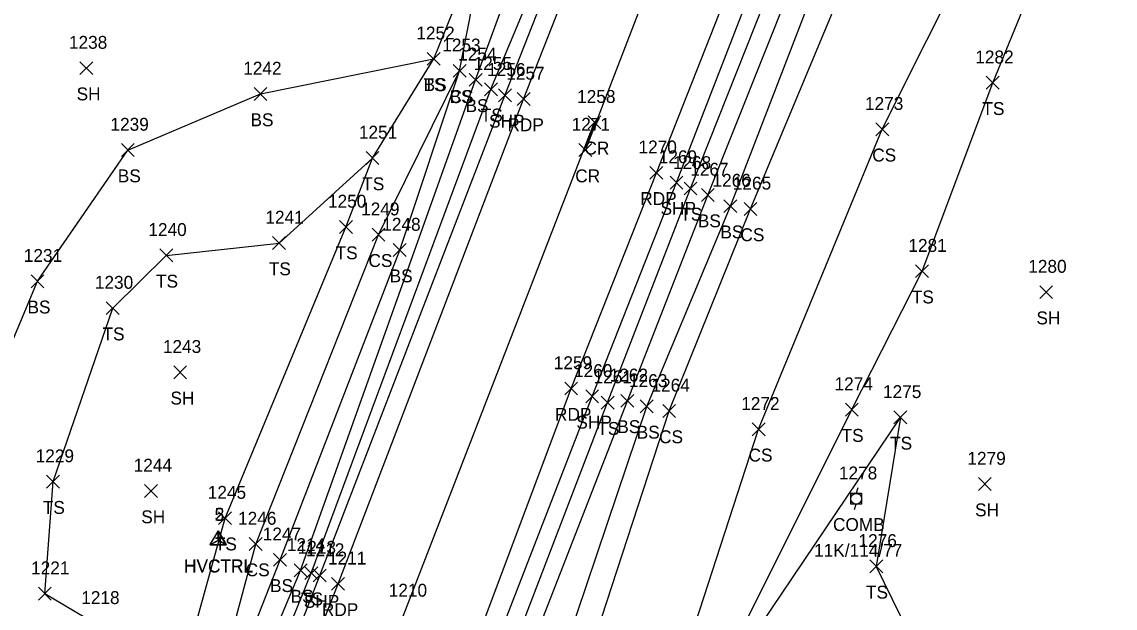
# Model space of a CAD drawing. Extents: x 1554917 to 1555870, y 813367 to 816333.
# Drawn here: x 1555023.3 to 1555192.9, y 813668.8 to 813759.7 of the extents above; entities that cross this region are included whole.
import ezdxf

# ---------------------------------------------------------------- set-up
doc = ezdxf.new("R2010")
doc.units = 0
for name, color, linetype in [('C_A', 7, 'Continuous'), ('C_I', 7, 'Continuous'), ('CPSM', 7, 'Continuous'), ('L_A', 7, 'Continuous'), ('L_I', 7, 'Continuous'), ('L_TIC', 7, 'Continuous'), ('LELB', 7, 'Continuous'), ('P_A', 7, 'Continuous'), ('P_I', 7, 'Continuous'), ('P_TIC', 7, 'Continuous'), ('PET', 7, 'Continuous'), ('PRC', 7, 'Continuous'), ('PSP', 7, 'Continuous'), ('U_A', 7, 'Continuous'), ('U_C', 7, 'Continuous'), ('U_I', 7, 'Continuous'), ('UP', 7, 'Continuous')]:
    doc.layers.add(name, color=color, linetype=linetype)

msp = doc.modelspace()

# ---------------------------------------------------------------- linework, layer by layer
at = {"layer": 'CPSM'}
for p, q in [((1555052.5, 813678.55), (1555053.75, 813680.71)), ((1555052.52, 813678.6), (1555053.77, 813680.76)), ((1555055, 813678.55), (1555053.75, 813680.71)), ((1555053.75, 813679.27), (1555053.75, 813680.71)), ((1555055.02, 813678.6), (1555053.77, 813680.76)), ((1555053.77, 813679.32), (1555053.77, 813680.76)), ((1555052.5, 813678.55), (1555053.75, 813679.27)), ((1555052.5, 813678.55), (1555055, 813678.55)), ((1555052.52, 813678.6), (1555053.77, 813679.32)), ((1555052.52, 813678.6), (1555055.02, 813678.6)), ((1555053.75, 813679.27), (1555053.75, 813679.27)), ((1555053.75, 813679.27), (1555055, 813678.55)), ((1555053.77, 813679.32), (1555053.77, 813679.32)), ((1555053.77, 813679.32), (1555055.02, 813678.6))]:
    msp.add_line(p, q, dxfattribs=at)
at = {"layer": 'L_TIC'}
for points in [[(1555086.17, 813752.94), (1555088.17, 813754.94)], [(1555088.17, 813752.94), (1555086.17, 813754.94)], [(1555086.17, 813752.94), (1555088.17, 813754.94)], [(1555088.17, 813752.94), (1555086.17, 813754.94)], [(1555032.29, 813751.5), (1555034.29, 813753.5)], [(1555034.29, 813751.5), (1555032.29, 813753.5)], [(1555090.18, 813751.08), (1555092.18, 813753.08)], [(1555092.18, 813751.08), (1555090.18, 813753.08)], [(1555090.18, 813751.08), (1555092.18, 813753.08)], [(1555092.18, 813751.08), (1555090.18, 813753.08)], [(1555092.66, 813749.68), (1555094.66, 813751.68)], [(1555094.66, 813749.68), (1555092.66, 813751.68)], [(1555095.05, 813748.22), (1555097.05, 813750.22)], [(1555097.05, 813748.22), (1555095.05, 813750.22)], [(1555172.86, 813749.23), (1555174.86, 813751.23)], [(1555174.86, 813749.23), (1555172.86, 813751.23)], [(1555059.31, 813747.49), (1555061.31, 813749.49)], [(1555061.31, 813747.49), (1555059.31, 813749.49)], [(1555155.74, 813742.02), (1555157.74, 813744.02)], [(1555157.74, 813742.02), (1555155.74, 813744.02)], [(1555038.73, 813738.79), (1555040.73, 813740.79)], [(1555040.73, 813738.79), (1555038.73, 813740.79)], [(1555076.68, 813737.56), (1555078.68, 813739.56)], [(1555078.68, 813737.56), (1555076.68, 813739.56)], [(1555076.68, 813737.56), (1555078.68, 813739.56)], [(1555078.68, 813737.56), (1555076.68, 813739.56)], [(1555126, 813732.84), (1555128, 813734.84)], [(1555128, 813732.84), (1555126, 813734.84)], [(1555128.69, 813731.82), (1555130.69, 813733.82)], [(1555130.69, 813731.82), (1555128.69, 813733.82)], [(1555132.19, 813730.1), (1555134.19, 813732.1)], [(1555134.19, 813730.1), (1555132.19, 813732.1)], [(1555135.3, 813729.66), (1555137.3, 813731.66)], [(1555137.3, 813729.66), (1555135.3, 813731.66)], [(1555072.55, 813726.86), (1555074.55, 813728.86)], [(1555074.55, 813726.86), (1555072.55, 813728.86)], [(1555077.61, 813725.66), (1555079.61, 813727.66)], [(1555079.61, 813725.66), (1555077.61, 813727.66)], [(1555062.18, 813724.38), (1555064.18, 813726.38)], [(1555064.18, 813724.38), (1555062.18, 813726.38)], [(1555044.69, 813722.46), (1555046.69, 813724.46)], [(1555046.69, 813722.46), (1555044.69, 813724.46)], [(1555080.89, 813723.28), (1555082.89, 813725.28)], [(1555082.89, 813723.28), (1555080.89, 813725.28)], [(1555161.91, 813720.01), (1555163.91, 813722.01)], [(1555163.91, 813720.01), (1555161.91, 813722.01)], [(1555024.72, 813718.45), (1555026.72, 813720.45)], [(1555026.72, 813718.45), (1555024.72, 813720.45)], [(1555181.16, 813716.76), (1555183.16, 813718.76)], [(1555183.16, 813716.76), (1555181.16, 813718.76)], [(1555036.39, 813714.28), (1555038.39, 813716.28)], [(1555038.39, 813714.28), (1555036.39, 813716.28)], [(1555046.85, 813704.33), (1555048.85, 813706.33)], [(1555048.85, 813704.33), (1555046.85, 813706.33)], [(1555113.13, 813699.62), (1555115.13, 813701.62)], [(1555115.13, 813699.62), (1555113.13, 813701.62)], [(1555116.2, 813699.9), (1555118.2, 813701.9)], [(1555118.2, 813699.9), (1555116.2, 813701.9)], [(1555119.2, 813699.04), (1555121.2, 813701.04)], [(1555121.2, 813699.04), (1555119.2, 813701.04)], [(1555151.02, 813698.54), (1555153.02, 813700.54)], [(1555153.02, 813698.54), (1555151.02, 813700.54)], [(1555122.68, 813698.33), (1555124.68, 813700.33)], [(1555124.68, 813698.33), (1555122.68, 813700.33)], [(1555158.54, 813697.33), (1555160.54, 813699.33)], [(1555160.54, 813697.33), (1555158.54, 813699.33)], [(1555136.56, 813695.49), (1555138.56, 813697.49)], [(1555138.56, 813695.49), (1555136.56, 813697.49)], [(1555027.13, 813687.37), (1555029.13, 813689.37)], [(1555029.13, 813687.37), (1555027.13, 813689.37)], [(1555171.64, 813686.99), (1555173.64, 813688.99)], [(1555173.64, 813686.99), (1555171.64, 813688.99)], [(1555042.32, 813685.92), (1555044.32, 813687.92)], [(1555044.32, 813685.92), (1555042.32, 813687.92)], [(1555053.81, 813681.71), (1555055.81, 813683.71)], [(1555055.81, 813681.71), (1555053.81, 813683.71)], [(1555058.57, 813677.69), (1555060.57, 813679.69)], [(1555060.57, 813677.69), (1555058.57, 813679.69)], [(1555062.34, 813675.25), (1555064.34, 813677.25)], [(1555064.34, 813675.25), (1555062.34, 813677.25)], [(1555065.52, 813673.6), (1555067.52, 813675.6)], [(1555067.52, 813673.6), (1555065.52, 813675.6)], [(1555067.18, 813673.18), (1555069.18, 813675.18)], [(1555069.18, 813673.18), (1555067.18, 813675.18)], [(1555154.8, 813674.23), (1555156.8, 813676.23)], [(1555156.8, 813674.23), (1555154.8, 813676.23)], [(1555025.85, 813669.99), (1555027.85, 813671.99)], [(1555027.85, 813669.99), (1555025.85, 813671.99)]]:
    msp.add_lwpolyline(points, dxfattribs=at)
at = {"layer": 'LELB'}
for points in [[(1555019.54, 813585.69), (1555024.77, 813597.99), (1555042.65, 813620.9), (1555048.58, 813631.85), (1555066.52, 813674.6), (1555093.66, 813750.68), (1555103.98, 813778.92), (1555100.94, 813788.26), (1555095.86, 813797.4), (1555100.34, 813804.26), (1555113.07, 813834.65), (1555120.88, 813859.4), (1555126.12, 813877.4), (1555144.96, 813909.35), (1555149.61, 813919.5), (1555153.95, 813930.09), (1555158.29, 813940)], [(1554960.86, 813387.22), (1554975.88, 813430.61), (1554997.67, 813492.71), (1555013.89, 813538.05), (1555028.68, 813579.18), (1555048.82, 813626.54), (1555068.18, 813674.18), (1555096.05, 813749.22), (1555111.01, 813785.1), (1555115.51, 813798.83), (1555119.3, 813812.87), (1555134.87, 813853.17), (1555141.95, 813870.8), (1555155.34, 813907.69), (1555153.32, 813917.67), (1555161.57, 813925.65), (1555168.92, 813938.89)], [(1555101.22, 813603.84), (1555111.95, 813631.93), (1555127.97, 813651.43), (1555152.02, 813699.54), (1555162.91, 813721.01), (1555173.86, 813750.23), (1555186.14, 813780.13), (1555202.44, 813820.35), (1555215.18, 813875.95), (1555215.28, 813897.96), (1555212.9, 813910.7), (1555212.19, 813917.21), (1555210.66, 813920.37), (1555207.16, 813922.92), (1555203.03, 813922.76), (1555199.5, 813919.6)], [(1554992.4, 813377.01), (1555009.62, 813423.34), (1555030.72, 813482.86), (1555047.7, 813528.1), (1555056, 813550.42), (1555062.05, 813566.99), (1555080.33, 813615.57), (1555099.41, 813662.25), (1555114.13, 813700.62), (1555127, 813733.84), (1555152.94, 813799.24), (1555168.16, 813840.25), (1555187.47, 813890.8), (1555199.5, 813919.6)], [(1555091.02, 813589.64), (1555093.93, 813609.08), (1555110.01, 813657.36), (1555123.68, 813699.33), (1555136.3, 813730.66), (1555163.02, 813794.74), (1555179.29, 813835.95), (1555197.25, 813886.69), (1555209.44, 813915.13), (1555210.66, 813920.37)], [(1554997.34, 813375.96), (1555001.03, 813380.2), (1555008.26, 813399.3), (1555016.85, 813422.36), (1555039.01, 813478.41), (1555055.21, 813525.71), (1555062.73, 813548.53), (1555066.84, 813564.4), (1555085.89, 813613.91), (1555101.8, 813661.36), (1555117.2, 813700.9), (1555129.69, 813732.82), (1555155.55, 813797.61), (1555171.4, 813838.65), (1555190.74, 813889.78), (1555201.42, 813914.42), (1555204.39, 813917.83), (1555206.44, 813916.94)], [(1555060.32, 813524.58), (1555067.83, 813537.87), (1555070.43, 813550.96), (1555072.05, 813560.86), (1555087.88, 813613.15), (1555106.35, 813658.95), (1555120.2, 813700.04), (1555133.19, 813731.1), (1555158.65, 813797.07), (1555174.38, 813837.99), (1555194.21, 813888.82), (1555206.44, 813916.94)], [(1555111.95, 813631.93), (1555123.2, 813652.42), (1555137.56, 813696.49), (1555156.74, 813743.02), (1555177.49, 813784.47), (1555191.84, 813829.42), (1555205.71, 813882.43), (1555212.9, 813910.7)], [(1554949.33, 813611.76), (1554977.21, 813618.67), (1554998.22, 813624.91), (1555016.24, 813625.01), (1555029.3, 813621.81), (1555040.32, 813624.75), (1555045.98, 813633.07), (1555049.32, 813640.6), (1555063.34, 813676.25), (1555081.89, 813724.28), (1555091.18, 813752.08), (1555095.69, 813774.96), (1555088.32, 813786.78), (1555082.82, 813809.08), (1555086.32, 813807.6), (1555081.46, 813811.86)], [(1554954.51, 813629.31), (1554971.74, 813631.07), (1554998.18, 813639.71), (1555016.83, 813638), (1555031.95, 813634.95), (1555041.94, 813634.59), (1555045.91, 813643.15), (1555048.09, 813658.42), (1555054.81, 813682.71), (1555073.55, 813727.86), (1555077.68, 813738.56), (1555087.17, 813753.94), (1555095.69, 813774.96)], [(1555045.91, 813643.15), (1555028.26, 813653.89), (1555014.84, 813665.72), (1555013.69, 813690.7), (1555025.72, 813719.45), (1555039.73, 813739.79), (1555060.31, 813748.49), (1555087.17, 813753.94)], [(1555049.32, 813640.6), (1555059.57, 813678.69), (1555078.61, 813726.66), (1555091.18, 813752.08)], [(1555048.09, 813658.42), (1555034.63, 813666.39), (1555026.85, 813670.99), (1555028.13, 813688.37), (1555037.39, 813715.28), (1555045.69, 813723.46), (1555063.18, 813725.38), (1555077.68, 813738.56)], [(1555156.68, 813641.57), (1555136.39, 813653.39), (1555127.97, 813651.43), (1555159.54, 813698.33), (1555155.8, 813675.23), (1555164.42, 813657.6)]]:
    msp.add_lwpolyline(points, dxfattribs=at)
at = {"layer": 'P_TIC'}
for points in [[(1555097.21, 813747.28), (1555099.21, 813749.28)], [(1555099.21, 813747.28), (1555097.21, 813749.28)], [(1555100.11, 813746.71), (1555102.11, 813748.71)], [(1555102.11, 813746.71), (1555100.11, 813748.71)], [(1555111.1, 813743.1), (1555113.1, 813745.1)], [(1555113.1, 813743.1), (1555111.1, 813745.1)], [(1555109.69, 813738.79), (1555111.69, 813740.79)], [(1555111.69, 813738.79), (1555109.69, 813740.79)], [(1555120.71, 813735.27), (1555122.71, 813737.27)], [(1555122.71, 813735.27), (1555120.71, 813737.27)], [(1555123.82, 813733.75), (1555125.82, 813735.75)], [(1555125.82, 813733.75), (1555123.82, 813735.75)], [(1555107.49, 813701.81), (1555109.49, 813703.81)], [(1555109.49, 813701.81), (1555107.49, 813703.81)], [(1555110.75, 813700.59), (1555112.75, 813702.59)], [(1555112.75, 813700.59), (1555110.75, 813702.59)], [(1555068.49, 813672.81), (1555070.49, 813674.81)], [(1555070.49, 813672.81), (1555068.49, 813674.81)], [(1555071.33, 813671.52), (1555073.33, 813673.52)], [(1555073.33, 813671.52), (1555071.33, 813673.52)]]:
    msp.add_lwpolyline(points, dxfattribs=at)
at = {"layer": 'PET'}
for points in [[(1554965.43, 813385.56), (1554980.95, 813429.92), (1555003.19, 813490.59), (1555019.55, 813535.73), (1555035.2, 813576.47), (1555053.52, 813624.76), (1555072.33, 813672.52), (1555101.11, 813747.71), (1555125.53, 813809.89), (1555141.72, 813851.12), (1555161.36, 813900.53), (1555183.5, 813956.99)], [(1554987.55, 813378.28), (1555004.34, 813425.43), (1555025.15, 813482.53), (1555042.33, 813529.78), (1555057.09, 813568.35), (1555075.57, 813617.35), (1555093.79, 813663.7), (1555108.49, 813702.81), (1555121.71, 813736.27), (1555147.41, 813801.52), (1555163.02, 813841.94), (1555182.57, 813892.25), (1555203.7, 813945.01)]]:
    msp.add_lwpolyline(points, dxfattribs=at)
at = {"layer": 'PRC'}
msp.add_lwpolyline([(1554976.76, 813382.18), (1554992.84, 813427.9), (1555014.07, 813486.01), (1555030.62, 813532.31), (1555046.37, 813573.08), (1555064.69, 813621.19), (1555082.41, 813667.53), (1555112.1, 813744.1), (1555110.69, 813739.79), (1555136.16, 813805.74), (1555152.52, 813846.93), (1555172.03, 813896.18), (1555193.96, 813951.2), (1555206.37, 813983.4), (1555218.13, 814013.22), (1555228.65, 814039.26), (1555237.93, 814064.31), (1555252.22, 814099.76), (1555265.8, 814135.89), (1555275.26, 814160.09), (1555297.17, 814214.77), (1555313.83, 814257.94), (1555329.72, 814298.26), (1555342.03, 814329.92)], dxfattribs=at)
at = {"layer": 'PSP'}
for points in [[(1554990.52, 813377.71), (1555007.26, 813424.1), (1555027.97, 813481.79), (1555045.41, 813528.93), (1555059.94, 813567), (1555096.82, 813663.08), (1555111.75, 813701.59), (1555124.82, 813734.75), (1555150.26, 813800.36), (1555166.19, 813840.91), (1555185.69, 813891.41), (1555197.67, 813922.42), (1555211.91, 813956.86)], [(1554963, 813386.3), (1554978.53, 813430.4), (1555000.44, 813491.39), (1555017.18, 813537.03), (1555032.55, 813577.93), (1555050.86, 813625.69), (1555069.49, 813673.81), (1555098.21, 813748.28), (1555122.69, 813810.6), (1555138.9, 813851.92), (1555160.79, 813906.47), (1555173.05, 813937.33)]]:
    msp.add_lwpolyline(points, dxfattribs=at)
at = {"layer": 'UP'}
for p, q in [((1555152.95, 813687.39), (1555152.7, 813686.56)), ((1555151.87, 813684.89), (1555151.87, 813686.56)), ((1555151.87, 813686.56), (1555153.54, 813686.56)), ((1555152.7, 813685.72), (1555152.7, 813685.72)), ((1555153.54, 813686.56), (1555153.54, 813684.89)), ((1555153.54, 813684.89), (1555151.87, 813684.89)), ((1555152.45, 813684.06), (1555152.7, 813684.89))]:
    msp.add_line(p, q, dxfattribs=at)
msp.add_circle((1555152.7, 813685.72), 0.833, dxfattribs=at)

# ---------------------------------------------------------------- texts
at = {"layer": 'C_A'}
for p in [(1555048.44, 813674.27), (1555048.46, 813674.32)]:
    msp.add_text('HVCTRL', height=2, dxfattribs=at).set_placement(p)
at = {"layer": 'C_I'}
for s, p in [('5', (1555053.18, 813682.27)), ('2', (1555053.21, 813682.32))]:
    msp.add_text(s, height=2, dxfattribs=at).set_placement(p)
at = {"layer": 'L_A'}
for s, p in [('TS', (1555085.58, 813748.94)), ('BS', (1555085.61, 813748.94)), ('SH', (1555031.78, 813747.5)), ('CS', (1555089.63, 813747.08)), ('BS', (1555089.63, 813747.08)), ('BS', (1555092.1, 813745.68)), ('TS', (1555094.46, 813744.22)), ('TS', (1555172.27, 813745.23)), ('BS', (1555058.75, 813743.49)), ('CS', (1555155.18, 813738.02)), ('BS', (1555038.17, 813734.79)), ('TS', (1555076.09, 813733.56)), ('TS', (1555076.09, 813733.56)), ('TS', (1555125.41, 813728.84)), ('BS', (1555128.13, 813727.82)), ('BS', (1555131.63, 813726.1)), ('CS', (1555134.74, 813725.66)), ('TS', (1555071.95, 813722.86)), ('CS', (1555077.05, 813721.66)), ('TS', (1555061.59, 813720.38)), ('BS', (1555080.33, 813719.28)), ('TS', (1555044.1, 813718.46)), ('TS', (1555161.32, 813716.01)), ('BS', (1555024.16, 813714.45)), ('SH', (1555180.65, 813712.76)), ('TS', (1555035.8, 813710.28)), ('SH', (1555046.34, 813700.33)), ('TS', (1555112.54, 813695.62)), ('BS', (1555115.64, 813695.9)), ('BS', (1555118.65, 813695.04)), ('CS', (1555122.12, 813694.33)), ('TS', (1555150.43, 813694.54)), ('TS', (1555157.95, 813693.33)), ('CS', (1555136, 813691.49)), ('TS', (1555026.54, 813683.37)), ('SH', (1555041.81, 813681.92)), ('SH', (1555171.13, 813682.99)), ('TS', (1555053.22, 813677.71)), ('CS', (1555058.01, 813673.69)), ('BS', (1555061.78, 813671.25)), ('BS', (1555064.96, 813669.6)), ('TS', (1555154.21, 813670.23)), ('TS', (1555066.59, 813669.18))]:
    msp.add_text(s, height=2, dxfattribs=at).set_placement(p)
at = {"layer": 'L_I'}
for s, p in [('1252', (1555084.47, 813756.94)), ('1252', (1555084.47, 813756.94)), ('1238', (1555030.59, 813755.5)), ('1253', (1555088.49, 813755.08)), ('1253', (1555088.49, 813755.08)), ('1254', (1555090.96, 813753.68)), ('1282', (1555171.16, 813753.23)), ('1242', (1555057.62, 813751.49)), ('1255', (1555093.36, 813752.22)), ('1273', (1555154.05, 813746.02)), ('1239', (1555037.03, 813742.79)), ('1251', (1555075.56, 813741.56)), ('1251', (1555075.56, 813741.56)), ('1268', (1555124.26, 813736.84)), ('1267', (1555126.95, 813735.82)), ('1266', (1555130.4, 813734.1)), ('1265', (1555133.56, 813733.66)), ('1250', (1555070.77, 813730.86)), ('1249', (1555075.91, 813729.66)), ('1241', (1555061.06, 813728.38)), ('1248', (1555079.19, 813727.28)), ('1240', (1555042.91, 813726.46)), ('1281', (1555160.79, 813724.01)), ('1231', (1555023.59, 813722.45)), ('1280', (1555179.38, 813720.76)), ('1230', (1555034.61, 813718.28)), ('1243', (1555045.16, 813708.33)), ('1261', (1555111.96, 813703.62)), ('1262', (1555114.45, 813703.9)), ('1263', (1555117.46, 813703.04)), ('1264', (1555120.94, 813702.33)), ('1274', (1555149.33, 813702.54)), ('1275', (1555156.85, 813701.33)), ('1272', (1555134.86, 813699.49)), ('1229', (1555025.43, 813691.37)), ('1244', (1555040.63, 813689.92)), ('1279', (1555169.94, 813690.99)), ('1245', (1555052.12, 813685.71)), ('1246', (1555056.82, 813681.69)), ('1247', (1555060.65, 813679.25)), ('1276', (1555153.05, 813678.23)), ('1214', (1555064.39, 813677.6)), ('1213', (1555066.06, 813677.18)), ('1221', (1555024.72, 813673.99)), ('1218', (1555032.5, 813669.39))]:
    msp.add_text(s, height=2, dxfattribs=at).set_placement(p)
at = {"layer": 'P_A'}
for s, p in [('SHP', (1555095.75, 813743.28)), ('RDP', (1555098.6, 813742.71)), ('CR', (1555110.54, 813739.1)), ('CR', (1555109.12, 813734.79)), ('RDP', (1555119.2, 813731.27)), ('SHP', (1555122.35, 813729.75)), ('RDP', (1555105.98, 813697.81)), ('SHP', (1555109.29, 813696.59)), ('SHP', (1555067.02, 813668.81)), ('RDP', (1555069.82, 813667.52))]:
    msp.add_text(s, height=2, dxfattribs=at).set_placement(p)
at = {"layer": 'P_I'}
for s, p in [('1256', (1555095.46, 813751.28)), ('1257', (1555098.42, 813750.71)), ('1258', (1555109.41, 813747.1)), ('1271', (1555108.56, 813742.79)), ('1270', (1555118.93, 813739.27)), ('1269', (1555122.07, 813737.75)), ('1259', (1555105.79, 813705.81)), ('1260', (1555108.93, 813704.59)), ('1212', (1555067.36, 813676.81)), ('1211', (1555070.77, 813675.52)), ('1210', (1555080.19, 813670.53))]:
    msp.add_text(s, height=2, dxfattribs=at).set_placement(p)
at = {"layer": 'U_A'}
msp.add_text('COMB', height=2, dxfattribs=at).set_placement((1555149.09, 813680.72))
at = {"layer": 'U_C'}
msp.add_text('11K/114/77', height=2, dxfattribs=at).set_placement((1555146.17, 813676.72))
at = {"layer": 'U_I'}
msp.add_text('1278', height=2, dxfattribs=at).set_placement((1555150.01, 813688.72))

doc.saveas('drawing.dxf')
